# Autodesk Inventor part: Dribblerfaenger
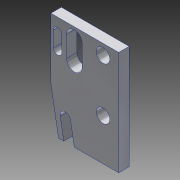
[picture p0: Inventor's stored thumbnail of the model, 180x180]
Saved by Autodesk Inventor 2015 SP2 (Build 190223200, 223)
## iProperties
Created: 2015-08
Part Number: Dribblerfaenger
Material: Aluminium 6061
Document SubType Name: Modeling
Designer: rYan
Mass: 1.03738 g
Surface Area: 5.60658 cm^2
Volume: 0.384216 cm^3
Density: 2.7 g/cm^3
Appearance: Aluminium - flach
Author: rYan
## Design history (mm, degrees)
sketch "Skizze1"
  geometry: L1 (-7, 10)-(6, 10); L2 (6, 10)-(6, -1.668); L3 (-7, -10)-(-7, 10); L4 (-9.6, 0)-(8.6, 0) reference; L5 (0, -14)-(0, 14) reference; L6 (1.5, 9.5)-(1.5, 2.5); L7 (0, 8)-(0, 4); L8 (3, 4)-(3, 8); L9 (-4, 8)-(-4, -2); L10 (2.236, -5.826)-(1.5, -10); L11 (3.531, -10)-(4.206, -6.174); L12 (6, -1.668)-(4.531, -10); L13 (4.7, 4.5)-(4.7, 7.5); L14 (5.5, 4.5)-(5.5, 7.5); L15 (3.9, 7.5)-(3.9, 4.5); L16 (4.531, -10)-(3.531, -10); L17 (1.5, -10)-(-7, -10); C1 r 1.3 at (-4, 8); C2 r 1.3 at (-4, -2); A1 r 1.5 centre (1.5, 8) between (3, 8) and (0, 8); A2 r 1.5 centre (1.5, 4) between (0, 4) and (3, 4); A3 r 1 centre (3.221, -6) between (4.206, -6.174) and (2.236, -5.826); A4 r 0.8 centre (4.7, 4.5) between (3.9, 4.5) and (5.5, 4.5); A5 r 0.8 centre (4.7, 7.5) between (5.5, 7.5) and (3.9, 7.5); 3 further points
  constraints: 34 end point, 12 point on circle, 10 tangent, 8 parallel, 7 centre point, 2 midpoint, 2 point on line, 2 vertical, 1 collinear, 1 equal radius, 1 horizontal, 1 perpendicular
  dimensions: "d0" = 20 distance of L3.start L1.start; "d1" = 7 distance between parallel lines of L3 L5; "d2" = 6 distance between parallel lines of L2 L5; "d3" = 3 distance between parallel lines of L8 L7; "d4" = 6 distance from line of point (1.5, 6) L4; "d7" = 4 distance of A2.centre A1.centre; "d8" = 2.6 diameter of C1; "d9" = 10 distance of L9.end L9.start; "d10" = 3 distance from line of L3 L9.start; "d16" = 1 radius of A3; "d18" = 1.5 distance between parallel lines of L5 L6; "d23" = 3 distance of L13.start L13.end; "d24" = 0.8 radius of A5; "d25" = 1.3 distance between parallel lines of L2 L13; "d26" = 4 distance from line of L1 point (4.7, 6); "d28" = 1.5 distance from line of L5 L10.end; "d29" = 1 distance of L12.end L11.start; "d30" = 10 distance between parallel lines of L17 L4; "d31" = 2 distance from line of L9.end L4; "d32" = 10 deg angle of L5 L12; "d33" = 4 distance from line of L17 A3.centre
extrude "Extrusion1" new body sketch "Skizze1" distance "d11" = 2; taper "d12" = 0 deg
node "Volumenkörper1"
other parameters: "d13" = 8, "d22" = 8, "d27" = 3.5
